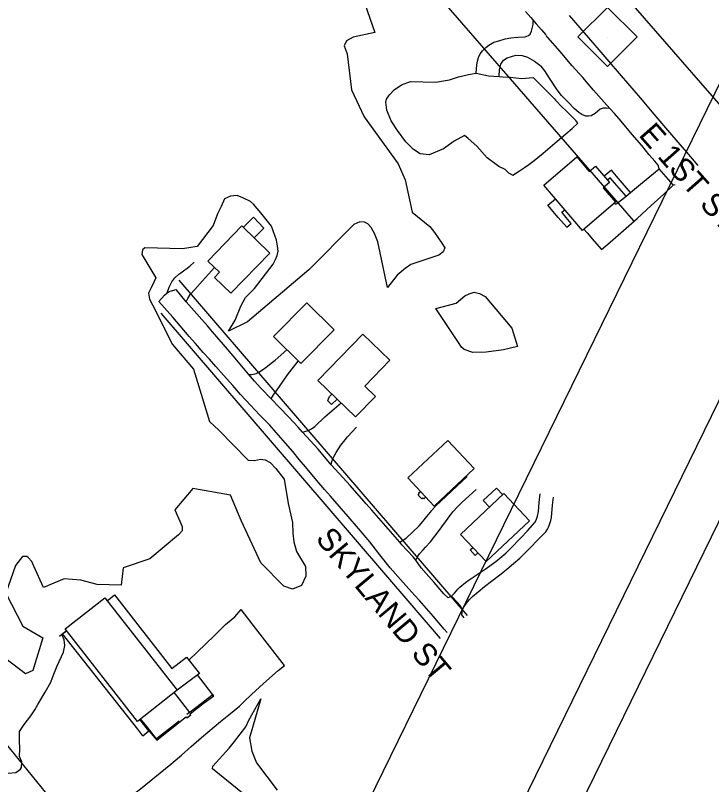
# Model space of a CAD drawing. Extents: x 1517485 to 1521905, y 636528 to 640355.
# Drawn here: x 1520903 to 1521396, y 637499 to 638045 of the extents above; entities that cross this region are included whole.
import ezdxf

# ---------------------------------------------------------------- set-up
doc = ezdxf.new("R2010")
doc.units = 0
for name, color, linetype in [('CTL Sheet Border CELL', 7, 'Continuous'), ('Default', 7, 'Continuous'), ('Exist Building', 7, 'Continuous'), ('Exist Building Metal Canopy', 7, 'Continuous'), ('Exist Other Culture Area Outline', 7, 'Continuous'), ('Exist Right of Way Line', 7, 'Continuous'), ('Exist Roads Curbs', 7, 'Continuous'), ('Exist Roads EOP', 7, 'Continuous'), ('Exist Roads EOP Other', 7, 'Continuous'), ('Exist Roads EOP Text', 7, 'Continuous'), ('Exist Roads Soil', 7, 'Continuous'), ('Exist Vegetation Woods Line', 7, 'Continuous'), ('Scratch_Level_3', 7, 'Continuous'), ('Sheet Plot Border Outside CELL', 7, 'Continuous')]:
    doc.layers.add(name, color=color, linetype=linetype)

msp = doc.modelspace()

# ---------------------------------------------------------------- linework, layer by layer
at = {"layer": 'CTL Sheet Border CELL'}
msp.add_lwpolyline([(1521847.18, 638683.19), (1518862.95, 640142.72), (1517841.29, 638053.77), (1520825.52, 636594.25)], close=True, dxfattribs=at)
at = {"layer": 'Default'}
msp.add_line((1521322.27, 638029.18), (1521322.27, 638029.18), dxfattribs=at)
msp.add_lwpolyline([(1521301.41, 638029.25), (1521322.38, 638050.22), (1521343.38, 638029.22), (1521322.41, 638008.25)], close=True, dxfattribs=at)
at = {"layer": 'Exist Building'}
for p, q in [((1520933.95, 637604.64), (1520938.82, 637608.58)), ((1521041.91, 637562.49), (1521042.76, 637563.12))]:
    msp.add_line(p, q, dxfattribs=at)
for points in [[(1521304.71, 637892.12), (1521277.21, 637924.09), (1521300.6, 637944.2), (1521309.5, 637933.85), (1521313.92, 637937.66), (1521323.81, 637926.17), (1521319.35, 637922.34), (1521328.07, 637912.2)], [(1521039.06, 637870.46), (1521063.09, 637895.34), (1521083, 637876.09), (1521055.43, 637847.56), (1521043.77, 637858.84), (1521047.29, 637862.48)], [(1521128.69, 637821.78), (1521104.98, 637797.73), (1521085.56, 637816.86), (1521109.27, 637840.92)], [(1521117.18, 637785.88), (1521148.97, 637818.67), (1521168.07, 637800.15), (1521150.32, 637781.84), (1521157.89, 637774.5), (1521143.85, 637760.02)], [(1521227.95, 637723.52), (1521199.62, 637696.86), (1521180.94, 637716.71), (1521209.27, 637743.37)], [(1521267.06, 637686.41), (1521236.29, 637657.51), (1521218.19, 637676.78), (1521248.96, 637705.68)], [(1520989.13, 637544.27), (1520937.94, 637609.71), (1520966.18, 637631.8), (1521017.37, 637566.36)]]:
    msp.add_lwpolyline(points, close=True, dxfattribs=at)
for points in [[(1521041.91, 637562.49), (1521026.29, 637550.64), (1521017.27, 637562.22), (1521015.25, 637564.7)], [(1521026.29, 637550.64), (1521025.85, 637550.31), (1521024.26, 637549.15)], [(1521018.75, 637544.42), (1521013.29, 637540.11), (1521002.72, 637531.96), (1520996.02, 637540.31), (1520991.38, 637546.03)]]:
    msp.add_lwpolyline(points, dxfattribs=at)
at = {"layer": 'Exist Building Metal Canopy'}
msp.add_lwpolyline([(1520967.75, 637629.71), (1520972.97, 637633.91), (1521013.7, 637581.8), (1521023.92, 637589.86), (1521033.09, 637578.13), (1521017.37, 637566.36)], dxfattribs=at)
at = {"layer": 'Exist Other Culture Area Outline'}
for p, q in [((1521126.85, 637768.86), (1521130.86, 637772.62)), ((1521228.65, 637661.84), (1521230.55, 637663.62)), ((1520936.15, 637606.28), (1520938.88, 637608.51))]:
    msp.add_line(p, q, dxfattribs=at)
for points in [[(1521252.24, 637932.9), (1521249.94, 637935.36), (1521245.4, 637937.48), (1521237.11, 637943.68), (1521229.74, 637951.93), (1521223.71, 637957.18), (1521220.95, 637959.4), (1521213.77, 637955.5), (1521206.06, 637949.97), (1521196.11, 637945.65), (1521189.64, 637946.47), (1521184.88, 637949.59), (1521179.52, 637954.82), (1521173.62, 637962.92), (1521168.97, 637969.83), (1521166.06, 637977.47), (1521165.29, 637982.94), (1521165.85, 637985.2), (1521167.96, 637988.33), (1521171.26, 637991.87), (1521176.33, 637995.37), (1521182.68, 637997.73), (1521200.45, 637997.26), (1521210.45, 637998.79), (1521216.84, 638000.86), (1521223.89, 638002.64), (1521229.24, 638003.5), (1521238.06, 638001.76), (1521245.58, 638001.29), (1521248.14, 638001.04)], [(1521248.14, 638001.04), (1521253.41, 638000.66), (1521257.41, 638000.25), (1521261.47, 637999.68), (1521269.71, 638000.51), (1521276.48, 637993.54), (1521281.19, 637988.87), (1521284.77, 637985.31), (1521285.66, 637984.35), (1521286.43, 637983.46), (1521289.63, 637980.18), (1521293.6, 637976.52), (1521299.89, 637969.92)], [(1521248.14, 638001.04), (1521253.41, 638000.66), (1521257.41, 638000.25), (1521261.47, 637999.68), (1521269.71, 638000.51), (1521276.48, 637993.54), (1521281.19, 637988.87), (1521284.77, 637985.31), (1521285.66, 637984.35), (1521286.43, 637983.46), (1521289.63, 637980.18), (1521293.6, 637976.52), (1521299.89, 637969.92)], [(1521252.24, 637932.9), (1521255.31, 637931.26), (1521260.12, 637934.43), (1521263.68, 637936.76), (1521266.66, 637938.83), (1521270.31, 637941.62), (1521273.11, 637943.73), (1521276.88, 637947), (1521281.85, 637951.23), (1521286.72, 637955.48), (1521292.97, 637960.59), (1521297.25, 637964.35), (1521301.43, 637968.18), (1521299.89, 637969.92)], [(1521338.62, 637919.08), (1521334.41, 637923.97), (1521328.74, 637930.55), (1521325.15, 637934.86), (1521320.07, 637930.51)], [(1521335.56, 637916.48), (1521327.42, 637925.82), (1521324.38, 637929.37), (1521322.46, 637927.73)], [(1521293.68, 637894.34), (1521287.5, 637901.29), (1521280.11, 637909.99), (1521285.48, 637914.48)], [(1521293.68, 637894.34), (1521296.69, 637897.11), (1521293.16, 637901.36), (1521290.13, 637904.96), (1521292.16, 637906.71)], [(1521071.88, 637886.85), (1521078.78, 637893.74), (1521071.37, 637901.44), (1521064.26, 637894.21)], [(1521126.85, 637768.86), (1521123.98, 637771.65), (1521124.71, 637772.33), (1521124.41, 637772.61), (1521125.66, 637774.69), (1521127.13, 637776.24)], [(1521238.66, 637696), (1521234.18, 637700.8), (1521243.76, 637709.61), (1521248.12, 637704.89)], [(1521188.18, 637704.62), (1521189.01, 637705.43), (1521188.49, 637705.97), (1521189.84, 637707.25)], [(1521188.18, 637704.62), (1521190.85, 637701.93), (1521191.61, 637702.64), (1521192.23, 637702), (1521193.57, 637703.29)], [(1521228.65, 637661.84), (1521225.1, 637665.7), (1521227, 637667.4)], [(1520993.11, 637534), (1520997.38, 637537.61), (1520990.87, 637545.64)]]:
    msp.add_lwpolyline(points, dxfattribs=at)
at = {"layer": 'Exist Right of Way Line'}
for p, q in [((1521214.06, 638197.45), (1521416.61, 637964.14)), ((1521112.91, 638161.42), (1521340.77, 637898.96)), ((1521018.53, 637856.92), (1521222.82, 637619.27)), ((1521005.75, 637833.44), (1521203.86, 637602.97)), ((1520826.07, 637613.79), (1520951.09, 637460.92))]:
    msp.add_line(p, q, dxfattribs=at)
at = {"layer": 'Exist Roads Curbs'}
for points in [[(1520993.11, 637534), (1520989.41, 637538.61), (1520936.15, 637606.28)], [(1520942.1, 637456.3), (1520943.97, 637457.77), (1520946.78, 637459.87), (1520950.54, 637462.91), (1520954.49, 637466.39), (1520963.19, 637473.68), (1520971.08, 637480.08), (1520978.78, 637486.34), (1520985.32, 637491.64), (1520991.35, 637496.54), (1521012.83, 637513.94), (1521014.49, 637515.26)]]:
    msp.add_lwpolyline(points, dxfattribs=at)
at = {"layer": 'Exist Roads EOP'}
for points in [[(1521264.32, 638047.38), (1521268.1, 638042.93), (1521271.85, 638038.57), (1521275.53, 638034.29), (1521278.69, 638030.63)], [(1521295.2, 638044.39), (1521305.75, 638032.06), (1521313.4, 638023.38), (1521321.86, 638013.56), (1521332.1, 638001.61), (1521345.53, 637985.98), (1521355.24, 637974.63), (1521367.87, 637959.76), (1521378.37, 637947.63), (1521386.41, 637938.18)], [(1521370.27, 637924.31), (1521368.94, 637924.49), (1521359.08, 637935.85), (1521358.26, 637938.29), (1521356, 637941.3), (1521351.99, 637945.78), (1521346.68, 637952.25), (1521339.96, 637960.16), (1521332.06, 637969.54), (1521327.27, 637974.95), (1521324.08, 637978.5), (1521319.93, 637983.08), (1521312.47, 637991.57), (1521304.88, 638000.51), (1521297.36, 638008.83), (1521288.77, 638018.81), (1521280.16, 638028.83), (1521278.96, 638030.23)], [(1521024.71, 637818.38), (1521014.21, 637830.63), (1521004.48, 637841.77), (1521008.29, 637846.16), (1521010.17, 637847.92), (1521012.45, 637849.19), (1521016.76, 637850.39)], [(1521083.92, 637772.74), (1521076.74, 637780.35), (1521072.18, 637785.23), (1521067.94, 637790.25), (1521061.93, 637797.42), (1521057.02, 637803.31), (1521050.2, 637811.26), (1521045.42, 637816.72), (1521042.31, 637820.3), (1521038.76, 637824.42), (1521034.94, 637828.95), (1521031.23, 637833.02), (1521023.86, 637841.59), (1521016.76, 637850.39)], [(1521069.51, 637768.15), (1521062.34, 637775.86), (1521056.78, 637782.16), (1521050.18, 637789.6), (1521044.76, 637795.68), (1521040.21, 637800.83), (1521035.89, 637805.66), (1521030.37, 637811.97), (1521025.8, 637817.06), (1521024.71, 637818.38)], [(1521106.26, 637749.22), (1521103.09, 637752.71), (1521096.47, 637759.82), (1521090.02, 637766.76), (1521083.92, 637772.74)], [(1521087.64, 637749.05), (1521082.98, 637754.05), (1521075.69, 637761.56), (1521069.51, 637768.15)], [(1521188.74, 637630.34), (1521183.47, 637636.15), (1521175.65, 637644.85), (1521168.37, 637653.14), (1521161.03, 637662.27), (1521153.83, 637671.51), (1521145.94, 637680.99), (1521138.57, 637689.48), (1521132.29, 637696.67), (1521126.15, 637703.76), (1521121.86, 637708.52), (1521115.1, 637716.42), (1521108.28, 637724.63), (1521103.82, 637729.78), (1521099.25, 637735.54), (1521094.27, 637741.44), (1521087.64, 637749.05)], [(1521220.9, 637617.62), (1521219.11, 637619.69), (1521219.72, 637623.28), (1521218.53, 637625.71), (1521216.41, 637628.24), (1521211.94, 637633.03), (1521209.39, 637631.68), (1521206.41, 637634.64), (1521199.45, 637642.63), (1521193.87, 637649.1), (1521190.4, 637653.14), (1521186.57, 637658.47), (1521184.68, 637660.74), (1521176.72, 637669.39), (1521175.11, 637671.13), (1521163.67, 637684.38), (1521155.28, 637694), (1521151.44, 637698.47), (1521139.92, 637711.27), (1521135.14, 637716.72), (1521126.64, 637726.15), (1521117.23, 637737.11), (1521106.26, 637749.22)], [(1521208.79, 637607.21), (1521206.71, 637609.61), (1521199.01, 637618.6), (1521189.15, 637629.87), (1521188.74, 637630.34)]]:
    msp.add_lwpolyline(points, dxfattribs=at)
at = {"layer": 'Exist Roads EOP Other'}
for points in [[(1521328.03, 637910.86), (1521328.96, 637911.27), (1521335.56, 637916.48), (1521338.62, 637919.08), (1521345.73, 637924.94), (1521359.08, 637935.85)], [(1521305.73, 637892.99), (1521307.88, 637890.43), (1521312.87, 637884.6), (1521318.26, 637878.57), (1521324.31, 637883.9), (1521333.85, 637892.08), (1521343.38, 637900.55), (1521353.4, 637909.71), (1521362.3, 637917.85), (1521368.93, 637924.11), (1521368.94, 637924.49)], [(1521328.03, 637910.86), (1521327.11, 637911.11), (1521326.92, 637911.22)], [(1521043.76, 637605.07), (1521051.55, 637612.8), (1521058.22, 637618.3), (1521062.7, 637623.63)], [(1521076.1, 637605.95), (1521072.82, 637610.36), (1521062.7, 637623.63)], [(1520897.58, 637507.45), (1520903.05, 637508.09), (1520906.37, 637510.39), (1520906.96, 637511.46), (1520907.29, 637515.54), (1520905.64, 637519.33), (1520905.75, 637524.8), (1520905.52, 637530.6), (1520905.5, 637537), (1520908.88, 637542.08), (1520913.61, 637548.24), (1520916.42, 637552.49), (1520918.56, 637556.21), (1520923.78, 637564.84), (1520927.7, 637571.98), (1520929.03, 637575.23), (1520932.26, 637583.69), (1520936.87, 637593.23), (1520937.65, 637597.95), (1520937.16, 637601.94), (1520935.7, 637605.9), (1520936.15, 637606.28)], [(1521043.76, 637605.07), (1521037.7, 637599.09), (1521025.74, 637587.52)], [(1521088.96, 637580.19), (1521093.46, 637583.79), (1521076.1, 637605.95)], [(1521014.49, 637515.26), (1521020.42, 637520.35), (1521027.38, 637526.49), (1521034.61, 637532.73), (1521048.01, 637544.05), (1521054.09, 637548.94), (1521061.51, 637555.03), (1521064.91, 637558.21), (1521069.97, 637563.24), (1521078.52, 637571.03), (1521088.96, 637580.19)], [(1521042.76, 637563.12), (1521036.56, 637570.98), (1521031.75, 637577.13)], [(1521038.2, 637558.61), (1521043.32, 637562.46), (1521042.8, 637563.06), (1521042.76, 637563.12)], [(1521031.24, 637553.3), (1521035.82, 637556.84), (1521038.2, 637558.61)], [(1521019.79, 637544.29), (1521023.63, 637547.4), (1521024.13, 637546.73), (1521027.12, 637548.93), (1521026.61, 637549.6), (1521031.24, 637553.3)], [(1520997.38, 637537.61), (1520998.98, 637535.63), (1521002.91, 637530.96), (1521007.8, 637534.97), (1521014.48, 637540.16), (1521019.79, 637544.29)]]:
    msp.add_lwpolyline(points, dxfattribs=at)
at = {"layer": 'Exist Roads Soil'}
msp.add_line((1521246.98, 637648.85), (1521250.98, 637652.02), dxfattribs=at)
for points in [[(1521264.1, 638029.37), (1521266.42, 638030.2), (1521267.66, 638031.18), (1521268.61, 638033.25), (1521269.35, 638036.11)], [(1521269.35, 638036.11), (1521269.66, 638038.05), (1521269.72, 638040.93)], [(1521229.24, 638003.5), (1521229.67, 638009.48), (1521230.16, 638012.11), (1521230.96, 638014.74), (1521232.21, 638017.35), (1521233.82, 638019.48), (1521236.15, 638021.75), (1521238.19, 638023.36), (1521241.95, 638025.49), (1521245.35, 638026.59), (1521249.81, 638027.94), (1521253.78, 638028.68), (1521258.91, 638029.16), (1521264.1, 638029.37)], [(1521245.58, 638001.29), (1521245.92, 638006.17), (1521246.88, 638009.88), (1521248.58, 638012.73), (1521251.17, 638014.47), (1521257.33, 638016.24), (1521261.91, 638016.02), (1521265.61, 638014.84), (1521270.67, 638012.05), (1521275.5, 638008.55)], [(1521324.08, 637978.5), (1521321.8, 637978.75), (1521319.4, 637978.67), (1521317.25, 637977.95), (1521313.65, 637975.03), (1521310.9, 637973.44), (1521309.04, 637973.17), (1521307.12, 637973.22), (1521304.27, 637974.37), (1521302.2, 637975.65), (1521299.01, 637978.38), (1521294.2, 637983.16), (1521289.76, 637987.72), (1521286.66, 637991.65), (1521281.24, 638000.08), (1521278.08, 638005.13), (1521275.5, 638008.55)], [(1521010.17, 637847.92), (1521011.58, 637851.82), (1521013.63, 637855.7), (1521015.79, 637858.6), (1521018.53, 637861.06), (1521019.97, 637862.02), (1521026.38, 637866.83), (1521029.48, 637869.6)], [(1521023.86, 637841.59), (1521024.89, 637843.93), (1521026.68, 637846.81), (1521030, 637850.37), (1521035.31, 637856.48), (1521043.88, 637865.79)], [(1521067.94, 637790.25), (1521068.63, 637790.04), (1521070.07, 637790.01), (1521072.34, 637790.46), (1521073.29, 637790.79), (1521075.29, 637791.67), (1521078.47, 637793.81), (1521081.39, 637795.96), (1521083.99, 637798.12), (1521086.91, 637800.31), (1521095.02, 637807.54)], [(1521083.92, 637772.74), (1521084.14, 637773.25), (1521085.74, 637775.68), (1521088.23, 637779.1), (1521089.93, 637781.47), (1521092.9, 637786.12), (1521095.69, 637789.85), (1521103.16, 637799.52)], [(1521106.26, 637749.22), (1521107.97, 637749.59), (1521110.29, 637750.4), (1521112.51, 637751.59), (1521114.89, 637753.3), (1521122.04, 637759.96), (1521133.7, 637769.87)], [(1521126.64, 637726.15), (1521127.04, 637728.36), (1521127.65, 637730.25), (1521128.56, 637732.18), (1521130.08, 637734.7), (1521133.46, 637739.89), (1521136.46, 637743.76), (1521138.04, 637745.81), (1521144.42, 637752.73)], [(1521198.23, 637694.26), (1521200.74, 637696.96), (1521204.27, 637700.32), (1521207.84, 637703.56), (1521211.91, 637707.4), (1521223.03, 637717.73)], [(1521186.57, 637658.47), (1521187.7, 637660.89), (1521189.06, 637663), (1521191.69, 637665.79), (1521193.39, 637667.62), (1521196.84, 637671.58), (1521203.19, 637679.57), (1521209.43, 637688.35), (1521212.76, 637692.73), (1521216.11, 637696.34), (1521219.5, 637699.56), (1521224.02, 637703.8), (1521229.39, 637708.47)], [(1521243.35, 637657.51), (1521250.24, 637663.48), (1521253.78, 637666.88), (1521260.8, 637674.08), (1521265.71, 637679.28), (1521270.85, 637685.13), (1521271.9, 637686.77), (1521272.87, 637689.56), (1521273.4, 637693.05), (1521274.02, 637699.33), (1521274.71, 637705.4)], [(1521250.98, 637652.02), (1521255.85, 637656.01), (1521260.28, 637660.01), (1521264.36, 637663.96), (1521267.92, 637667.44), (1521272.83, 637672.55), (1521276.44, 637676.28), (1521278.61, 637678.55), (1521279.81, 637680.35), (1521280.69, 637681.94), (1521281.35, 637683.67), (1521282.23, 637686.57), (1521282.7, 637688.8), (1521283.45, 637697.56), (1521284.17, 637703.2)], [(1521188.79, 637682.72), (1521191.46, 637685.78), (1521194.3, 637689.47), (1521197.8, 637693.76), (1521198.23, 637694.26)], [(1521175.11, 637671.13), (1521179.59, 637674.03), (1521188.79, 637682.72)], [(1521211.94, 637633.03), (1521213.92, 637635.09), (1521216.35, 637637.91), (1521217.75, 637639.31), (1521221.76, 637642.57), (1521224.27, 637644.52), (1521228.5, 637647.29), (1521235.7, 637652.02), (1521243.35, 637657.51)], [(1521219.72, 637623.28), (1521220.41, 637625.02), (1521222.44, 637627.92), (1521224.55, 637630.55), (1521226.61, 637632.65), (1521230.69, 637636.1), (1521235.33, 637639.93), (1521240.07, 637643.67), (1521246.98, 637648.85)]]:
    msp.add_lwpolyline(points, dxfattribs=at)
at = {"layer": 'Exist Vegetation Woods Line'}
for points in [[(1521023.27, 638237.65), (1521027.53, 638238.78), (1521037.79, 638248.11), (1521041.64, 638250.04), (1521045.03, 638250.51), (1521047.81, 638249.23), (1521059.01, 638241.9), (1521086.39, 638217.04), (1521110.27, 638193.05), (1521141.42, 638162.39), (1521177.5, 638118.31), (1521159.76, 638091.69), (1521149.47, 638072.15), (1521146.91, 638063.11), (1521157.39, 638032.39), (1521142.19, 638029.15), (1521137.39, 638026.58), (1521135.84, 638022.99), (1521137.75, 638017.23), (1521141.04, 637991.7), (1521150, 637972.66), (1521174.05, 637939.4), (1521179.02, 637927.94), (1521183.89, 637905.13)], [(1521110.76, 637864.29), (1521067.24, 637827.48), (1521053.7, 637820.64), (1521058.54, 637828.43), (1521062.56, 637838.37), (1521065.83, 637844.51), (1521072.27, 637851), (1521085.38, 637868.27), (1521087.05, 637871.57), (1521088.33, 637874.34), (1521088.9, 637877.36), (1521088.53, 637881.02), (1521087.83, 637885.17), (1521084.29, 637895.13), (1521076.57, 637904.7), (1521071.38, 637910.63), (1521069.46, 637912.55), (1521067.53, 637913.56), (1521066.32, 637914.12), (1521063.94, 637915.23), (1521059.98, 637916.83), (1521055.19, 637916.41), (1521051.02, 637914.43), (1521048.51, 637909.2), (1521046.05, 637903.92), (1521042.84, 637895.63), (1521031.61, 637880.68), (1521021.22, 637879.17), (1520994.4, 637879.84), (1520992.76, 637878.3), (1520992.3, 637875.07), (1521002.22, 637858.59), (1521000.88, 637855.58), (1520998.95, 637851.35), (1520997.05, 637847.75), (1520997.77, 637843.41), (1520999.96, 637839.4), (1521014.13, 637811.25), (1521029.02, 637793.85), (1521031.8, 637784.59), (1521040.19, 637756.66), (1521046.85, 637750.63), (1521067.67, 637729.24), (1521072.08, 637729.04), (1521076.36, 637730.08), (1521079.64, 637729.57), (1521083.36, 637727.64), (1521087.34, 637723.32), (1521093.17, 637715.95), (1521096.12, 637698.64)], [(1521183.89, 637905.13), (1521196.54, 637894.81), (1521199.84, 637890.75), (1521205.01, 637883.2), (1521207.03, 637879.91), (1521205.99, 637876.96), (1521202.78, 637874.5), (1521183.11, 637867.92), (1521178.96, 637865.05), (1521173.4, 637860.37), (1521166.5, 637851.61), (1521159.63, 637884.1), (1521157.3, 637889.86), (1521154.96, 637894.11), (1521152.54, 637896.76), (1521150.09, 637897.9), (1521146.81, 637898.12), (1521142.7, 637896.22), (1521110.76, 637864.29)], [(1521258.55, 637810), (1521248.58, 637807.52), (1521236.36, 637805.83), (1521226.97, 637805.62), (1521220.87, 637807.65), (1521218.86, 637809.45), (1521216.82, 637812.76), (1521200.79, 637836.77), (1521215.2, 637840.48), (1521221.32, 637845.74), (1521224.23, 637847.32), (1521227.97, 637848.31), (1521231.64, 637847.39), (1521235.76, 637845.42), (1521254.49, 637822.88), (1521258.55, 637810)], [(1521108.26, 637653.89), (1521108.65, 637647.25), (1521105.49, 637640.59), (1521099.22, 637638.01), (1521092.9, 637640.08), (1521076.56, 637656.54), (1521062.74, 637686.61), (1521055.12, 637704.5), (1521028.47, 637709.2), (1521015.8, 637694.19), (1521020.98, 637682.36), (1521020.82, 637679.22), (1521018.3, 637676.51), (1520997.92, 637659.47), (1520979, 637653.14), (1520977.6, 637640.87), (1520960.62, 637641.24), (1520949.19, 637644.37), (1520937.34, 637645.26), (1520922.6, 637639.01), (1520915.78, 637654.13), (1520914.35, 637657.64), (1520911.82, 637660.39), (1520910.75, 637661.01), (1520907.79, 637661.11), (1520902.81, 637654.81), (1520895.85, 637634.99), (1520907.98, 637611.66), (1520922.14, 637603.41), (1520914.98, 637580.38), (1520909.9, 637577.96), (1520895.88, 637588.65)], [(1521096.12, 637698.64), (1521099, 637685.2), (1521099.35, 637677.61), (1521100.02, 637671.43), (1521101.88, 637664.67), (1521108.26, 637653.89)], [(1521073.54, 637485.3), (1521042.33, 637510.62), (1521042.74, 637512.49), (1521054.18, 637525.2), (1521057.96, 637529.89), (1521065.95, 637540.35), (1521068.27, 637545.12), (1521076.7, 637560.26), (1521068.53, 637532.52), (1521070.19, 637523.23), (1521073.62, 637514.94), (1521088.34, 637495.6)]]:
    msp.add_lwpolyline(points, dxfattribs=at)
at = {"layer": 'Scratch_Level_3'}
msp.add_line((1521706.65, 638619.76), (1520952.83, 637078.47), dxfattribs=at)
at = {"layer": 'Sheet Plot Border Outside CELL'}
msp.add_lwpolyline([(1517484.74, 638166.53), (1520835.03, 636527.97), (1521905.33, 638716.38), (1518555.04, 640354.94)], close=True, dxfattribs=at)

# ---------------------------------------------------------------- texts
at = {"layer": 'Exist Roads EOP Text'}
for s, rotation, p in [('E 1ST ST', 311.4117, (1521343.88, 637959.49)), ('SKYLAND ST', 309.827, (1521114.88, 637673.37))]:
    msp.add_text(s, height=16, rotation=rotation, dxfattribs=at).set_placement(p)

doc.saveas('drawing.dxf')
